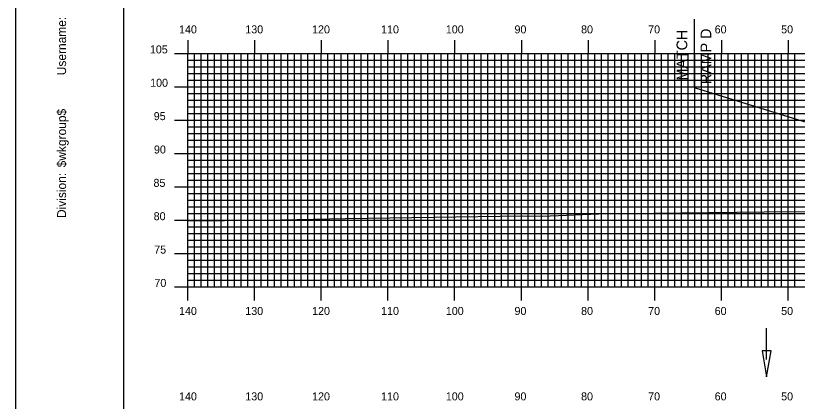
# Model space of a CAD drawing. Extents: x 1756282 to 1756625, y 442591 to 442811.
# Drawn here: x 1756281.8 to 1756398.9, y 442651.5 to 442709.3 of the extents above; entities that cross this region are included whole.
import ezdxf

# ---------------------------------------------------------------- set-up
doc = ezdxf.new("R2010")
doc.units = 0
for name, color, linetype in [('ANNOTATION', 7, 'Continuous'), ('BORDER', 7, 'Continuous'), ('D_Drainage_Ditch_Line', 7, 'Continuous'), ('D_Roadway_Centerline', 7, 'Continuous'), ('D_Roadway_SubGrade', 7, 'Continuous'), ('H_V ANNOTATION', 7, 'Continuous'), ('MAJOR', 7, 'Continuous'), ('MINOR', 7, 'Continuous'), ('PLOT BOUNDARY', 7, 'Continuous'), ('S_Roadway_Centerline', 7, 'Continuous')]:
    doc.layers.add(name, color=color, linetype=linetype)

msp = doc.modelspace()

# ---------------------------------------------------------------- linework, layer by layer
at = {"layer": 'BORDER'}
msp.add_lwpolyline([(1756297.97, 442596.67), (1756617.97, 442596.67), (1756617.97, 442806.67), (1756297.97, 442806.67)], close=True, dxfattribs=at)
at = {"layer": 'D_Drainage_Ditch_Line'}
msp.add_line((1756394.32, 442657.8), (1756394.32, 442662.5), dxfattribs=at)
msp.add_lwpolyline([(1756394.98, 442659.11), (1756393.67, 442659.11), (1756394.32, 442655.18)], close=True, dxfattribs=at)
at = {"layer": 'D_Roadway_Centerline'}
msp.add_lwpolyline([(1756383.48, 442698.56), (1756400.39, 442693.34), (1756401.23, 442693.06), (1756401.36, 442693.02), (1756402.56, 442692.63), (1756402.58, 442692.63), (1756402.66, 442692.6), (1756402.71, 442692.59), (1756403.03, 442692.48), (1756403.18, 442692.44), (1756404.11, 442692.13), (1756404.35, 442692.06), (1756405.57, 442691.66), (1756405.6, 442691.65), (1756405.76, 442691.6), (1756406.02, 442691.52), (1756407.03, 442691.19), (1756407.38, 442691.08), (1756409.6, 442690.36)], dxfattribs=at)
at = {"layer": 'D_Roadway_SubGrade'}
msp.add_line((1756383.48, 442708.78), (1756383.48, 442698.56), dxfattribs=at)
at = {"layer": 'MAJOR'}
for p, q in [((1756307.57, 442705.67), (1756307.57, 442703.67)), ((1756317.57, 442705.67), (1756317.57, 442703.67)), ((1756327.57, 442705.67), (1756327.57, 442703.67)), ((1756337.57, 442705.67), (1756337.57, 442703.67)), ((1756347.57, 442705.67), (1756347.57, 442703.67)), ((1756357.57, 442705.67), (1756357.57, 442703.67)), ((1756367.57, 442705.67), (1756367.57, 442703.67)), ((1756377.57, 442705.67), (1756377.57, 442703.67)), ((1756387.57, 442705.67), (1756387.57, 442703.67)), ((1756397.57, 442705.67), (1756397.57, 442703.67)), ((1756305.57, 442703.67), (1756307.57, 442703.67)), ((1756307.57, 442703.67), (1756587.57, 442703.67)), ((1756307.57, 442668.67), (1756307.57, 442703.67)), ((1756307.57, 442668.67), (1756307.57, 442703.67)), ((1756307.57, 442703.67), (1756587.57, 442703.67)), ((1756317.57, 442668.67), (1756317.57, 442703.67)), ((1756327.57, 442668.67), (1756327.57, 442703.67)), ((1756337.57, 442668.67), (1756337.57, 442703.67)), ((1756347.57, 442668.67), (1756347.57, 442703.67)), ((1756357.57, 442668.67), (1756357.57, 442703.67)), ((1756367.57, 442668.67), (1756367.57, 442703.67)), ((1756377.57, 442668.67), (1756377.57, 442703.67)), ((1756387.57, 442668.67), (1756387.57, 442703.67)), ((1756397.57, 442668.67), (1756397.57, 442703.67)), ((1756305.57, 442698.67), (1756307.57, 442698.67)), ((1756307.57, 442698.67), (1756587.57, 442698.67)), ((1756305.57, 442693.67), (1756307.57, 442693.67)), ((1756307.57, 442693.67), (1756587.57, 442693.67)), ((1756305.57, 442688.67), (1756307.57, 442688.67)), ((1756307.57, 442688.67), (1756587.57, 442688.67)), ((1756305.57, 442683.67), (1756307.57, 442683.67)), ((1756307.57, 442683.67), (1756587.57, 442683.67)), ((1756305.57, 442678.67), (1756307.57, 442678.67)), ((1756307.57, 442678.67), (1756587.57, 442678.67)), ((1756305.57, 442673.67), (1756307.57, 442673.67)), ((1756307.57, 442673.67), (1756587.57, 442673.67)), ((1756305.57, 442668.67), (1756307.57, 442668.67)), ((1756307.57, 442668.67), (1756587.57, 442668.67)), ((1756307.57, 442668.67), (1756587.57, 442668.67)), ((1756307.57, 442666.66), (1756307.57, 442668.67)), ((1756317.57, 442666.66), (1756317.57, 442668.67)), ((1756327.57, 442666.66), (1756327.57, 442668.67)), ((1756337.57, 442666.66), (1756337.57, 442668.67)), ((1756347.57, 442666.66), (1756347.57, 442668.67)), ((1756357.57, 442666.66), (1756357.57, 442668.67)), ((1756367.57, 442666.66), (1756367.57, 442668.67)), ((1756377.57, 442666.66), (1756377.57, 442668.67)), ((1756387.57, 442666.66), (1756387.57, 442668.67)), ((1756397.57, 442666.66), (1756397.57, 442668.67))]:
    msp.add_line(p, q, dxfattribs=at)
at = {"layer": 'MINOR'}
for p, q in [((1756307.57, 442702.67), (1756587.57, 442702.67)), ((1756307.57, 442702.67), (1756309.57, 442702.67)), ((1756308.57, 442668.67), (1756308.57, 442703.67)), ((1756309.57, 442668.67), (1756309.57, 442703.67)), ((1756310.57, 442668.67), (1756310.57, 442703.67)), ((1756311.57, 442668.67), (1756311.57, 442703.67)), ((1756312.57, 442668.67), (1756312.57, 442703.67)), ((1756313.57, 442668.67), (1756313.57, 442703.67)), ((1756314.57, 442668.67), (1756314.57, 442703.67)), ((1756315.57, 442668.67), (1756315.57, 442703.67)), ((1756316.57, 442668.67), (1756316.57, 442703.67)), ((1756318.57, 442668.67), (1756318.57, 442703.67)), ((1756319.57, 442668.67), (1756319.57, 442703.67)), ((1756320.57, 442668.67), (1756320.57, 442703.67)), ((1756321.57, 442668.67), (1756321.57, 442703.67)), ((1756322.57, 442668.67), (1756322.57, 442703.67)), ((1756323.57, 442668.67), (1756323.57, 442703.67)), ((1756324.57, 442668.67), (1756324.57, 442703.67)), ((1756325.57, 442668.67), (1756325.57, 442703.67)), ((1756326.57, 442668.67), (1756326.57, 442703.67)), ((1756328.57, 442668.67), (1756328.57, 442703.67)), ((1756329.57, 442668.67), (1756329.57, 442703.67)), ((1756330.57, 442668.67), (1756330.57, 442703.67)), ((1756331.57, 442668.67), (1756331.57, 442703.67)), ((1756332.57, 442668.67), (1756332.57, 442703.67)), ((1756333.57, 442668.67), (1756333.57, 442703.67)), ((1756334.57, 442668.67), (1756334.57, 442703.67)), ((1756335.57, 442668.67), (1756335.57, 442703.67)), ((1756336.57, 442668.67), (1756336.57, 442703.67)), ((1756338.57, 442668.67), (1756338.57, 442703.67)), ((1756339.57, 442668.67), (1756339.57, 442703.67)), ((1756340.57, 442668.67), (1756340.57, 442703.67)), ((1756341.57, 442668.67), (1756341.57, 442703.67)), ((1756342.57, 442668.67), (1756342.57, 442703.67)), ((1756343.57, 442668.67), (1756343.57, 442703.67)), ((1756344.57, 442668.67), (1756344.57, 442703.67)), ((1756345.57, 442668.67), (1756345.57, 442703.67)), ((1756346.57, 442668.67), (1756346.57, 442703.67)), ((1756348.57, 442668.67), (1756348.57, 442703.67)), ((1756349.57, 442668.67), (1756349.57, 442703.67)), ((1756350.57, 442668.67), (1756350.57, 442703.67)), ((1756351.57, 442668.67), (1756351.57, 442703.67)), ((1756352.57, 442668.67), (1756352.57, 442703.67)), ((1756353.57, 442668.67), (1756353.57, 442703.67)), ((1756354.57, 442668.67), (1756354.57, 442703.67)), ((1756355.57, 442668.67), (1756355.57, 442703.67)), ((1756356.57, 442668.67), (1756356.57, 442703.67)), ((1756358.57, 442668.67), (1756358.57, 442703.67)), ((1756359.57, 442668.67), (1756359.57, 442703.67)), ((1756360.57, 442668.67), (1756360.57, 442703.67)), ((1756361.57, 442668.67), (1756361.57, 442703.67)), ((1756362.57, 442668.67), (1756362.57, 442703.67)), ((1756363.57, 442668.67), (1756363.57, 442703.67)), ((1756364.57, 442668.67), (1756364.57, 442703.67)), ((1756365.57, 442668.67), (1756365.57, 442703.67)), ((1756366.57, 442668.67), (1756366.57, 442703.67)), ((1756368.57, 442668.67), (1756368.57, 442703.67)), ((1756369.57, 442668.67), (1756369.57, 442703.67)), ((1756370.57, 442668.67), (1756370.57, 442703.67)), ((1756371.57, 442668.67), (1756371.57, 442703.67)), ((1756372.57, 442668.67), (1756372.57, 442703.67)), ((1756373.57, 442668.67), (1756373.57, 442703.67)), ((1756374.57, 442668.67), (1756374.57, 442703.67)), ((1756375.57, 442668.67), (1756375.57, 442703.67)), ((1756376.57, 442668.67), (1756376.57, 442703.67)), ((1756378.57, 442668.67), (1756378.57, 442703.67)), ((1756379.57, 442668.67), (1756379.57, 442703.67)), ((1756380.57, 442668.67), (1756380.57, 442703.67)), ((1756381.57, 442668.67), (1756381.57, 442703.67)), ((1756382.57, 442668.67), (1756382.57, 442703.67)), ((1756383.57, 442668.67), (1756383.57, 442703.67)), ((1756384.57, 442668.67), (1756384.57, 442703.67)), ((1756385.57, 442668.67), (1756385.57, 442703.67)), ((1756386.57, 442668.67), (1756386.57, 442703.67)), ((1756388.57, 442668.67), (1756388.57, 442703.67)), ((1756389.57, 442668.67), (1756389.57, 442703.67)), ((1756390.57, 442668.67), (1756390.57, 442703.67)), ((1756391.57, 442668.67), (1756391.57, 442703.67)), ((1756392.57, 442668.67), (1756392.57, 442703.67)), ((1756393.57, 442668.67), (1756393.57, 442703.67)), ((1756394.57, 442668.67), (1756394.57, 442703.67)), ((1756395.57, 442668.67), (1756395.57, 442703.67)), ((1756396.57, 442668.67), (1756396.57, 442703.67)), ((1756398.57, 442668.67), (1756398.57, 442703.67)), ((1756307.57, 442701.67), (1756587.57, 442701.67)), ((1756307.57, 442701.67), (1756309.57, 442701.67)), ((1756307.57, 442700.67), (1756587.57, 442700.67)), ((1756307.57, 442700.67), (1756309.57, 442700.67)), ((1756307.57, 442699.67), (1756587.57, 442699.67)), ((1756307.57, 442699.67), (1756309.57, 442699.67)), ((1756307.57, 442697.67), (1756587.57, 442697.67)), ((1756307.57, 442697.67), (1756309.57, 442697.67)), ((1756307.57, 442696.67), (1756587.57, 442696.67)), ((1756307.57, 442696.67), (1756309.57, 442696.67)), ((1756307.57, 442695.67), (1756587.57, 442695.67)), ((1756307.57, 442695.67), (1756309.57, 442695.67)), ((1756307.57, 442694.67), (1756587.57, 442694.67)), ((1756307.57, 442694.67), (1756309.57, 442694.67)), ((1756307.57, 442692.67), (1756587.57, 442692.67)), ((1756307.57, 442692.67), (1756309.57, 442692.67)), ((1756307.57, 442691.67), (1756587.57, 442691.67)), ((1756307.57, 442691.67), (1756309.57, 442691.67)), ((1756307.57, 442690.67), (1756587.57, 442690.67)), ((1756307.57, 442690.67), (1756309.57, 442690.67)), ((1756307.57, 442689.67), (1756587.57, 442689.67)), ((1756307.57, 442689.67), (1756309.57, 442689.67)), ((1756307.57, 442687.67), (1756587.57, 442687.67)), ((1756307.57, 442687.67), (1756309.57, 442687.67)), ((1756307.57, 442686.67), (1756587.57, 442686.67)), ((1756307.57, 442686.67), (1756309.57, 442686.67)), ((1756307.57, 442685.67), (1756587.57, 442685.67)), ((1756307.57, 442685.67), (1756309.57, 442685.67)), ((1756307.57, 442684.67), (1756587.57, 442684.67)), ((1756307.57, 442684.67), (1756309.57, 442684.67)), ((1756307.57, 442682.67), (1756587.57, 442682.67)), ((1756307.57, 442682.67), (1756309.57, 442682.67)), ((1756307.57, 442681.67), (1756587.57, 442681.67)), ((1756307.57, 442681.67), (1756309.57, 442681.67)), ((1756307.57, 442680.67), (1756587.57, 442680.67)), ((1756307.57, 442680.67), (1756309.57, 442680.67)), ((1756307.57, 442679.67), (1756587.57, 442679.67)), ((1756307.57, 442679.67), (1756309.57, 442679.67)), ((1756307.57, 442677.67), (1756587.57, 442677.67)), ((1756307.57, 442677.67), (1756309.57, 442677.67)), ((1756307.57, 442676.67), (1756587.57, 442676.67)), ((1756307.57, 442676.67), (1756309.57, 442676.67)), ((1756307.57, 442675.67), (1756587.57, 442675.67)), ((1756307.57, 442675.67), (1756309.57, 442675.67)), ((1756307.57, 442674.67), (1756587.57, 442674.67)), ((1756307.57, 442674.67), (1756309.57, 442674.67)), ((1756307.57, 442672.67), (1756587.57, 442672.67)), ((1756307.57, 442672.67), (1756309.57, 442672.67)), ((1756307.57, 442671.67), (1756587.57, 442671.67)), ((1756307.57, 442671.67), (1756309.57, 442671.67)), ((1756307.57, 442670.67), (1756587.57, 442670.67)), ((1756307.57, 442670.67), (1756309.57, 442670.67)), ((1756307.57, 442669.67), (1756587.57, 442669.67)), ((1756307.57, 442669.67), (1756309.57, 442669.67))]:
    msp.add_line(p, q, dxfattribs=at)
at = {"layer": 'PLOT BOUNDARY'}
msp.add_lwpolyline([(1756281.78, 442590.55), (1756621.78, 442590.55), (1756621.78, 442810.55), (1756281.78, 442810.55)], close=True, dxfattribs=at)
at = {"layer": 'S_Roadway_Centerline'}
msp.add_lwpolyline([(1756307.57, 442678.65), (1756308.9, 442678.63), (1756313.08, 442678.64), (1756319.12, 442678.69), (1756331.23, 442678.95), (1756357.71, 442679.32), (1756360.7, 442679.28), (1756369.19, 442679.62), (1756398.08, 442679.98), (1756402.56, 442679.91)], dxfattribs=at)

# ---------------------------------------------------------------- texts
at = {"layer": 'ANNOTATION'}
for s, p in [('RAMP D', (1756386.03, 442699.07)), ('MATCH', (1756382.43, 442699.61))]:
    msp.add_text(s, height=1.6, rotation=90, dxfattribs=at).set_placement(p)
at = {"layer": 'BORDER'}
for s, p in [('Username:', (1756289.34, 442700.4)), ('Username:', (1756289.34, 442700.4)), ('$wkgroup$', (1756289.34, 442686.6)), ('$wkgroup$', (1756289.34, 442686.6)), ('Division:', (1756289.34, 442679)), ('Division:', (1756289.34, 442679))]:
    msp.add_text(s, height=1.339, rotation=90, dxfattribs=at).set_placement(p)
at = {"layer": 'H_V ANNOTATION'}
for s, p in [('140', (1756306.27, 442706.67)), ('130', (1756316.2, 442706.67)), ('120', (1756326.21, 442706.67)), ('110', (1756336.55, 442706.67)), ('100', (1756346.25, 442706.67)), ('90', (1756356.54, 442706.67)), ('80', (1756366.52, 442706.67)), ('70', (1756376.57, 442706.67)), ('60', (1756386.54, 442706.67)), ('50', (1756396.5, 442706.67)), ('105', (1756301.9, 442703.67)), ('100', (1756301.94, 442698.67)), ('95', (1756302.48, 442693.67)), ('90', (1756302.51, 442688.67)), ('85', (1756302.44, 442683.67)), ('80', (1756302.47, 442678.67)), ('75', (1756302.55, 442673.67)), ('70', (1756302.58, 442668.67)), ('140', (1756306.27, 442664.47)), ('130', (1756316.2, 442664.47)), ('120', (1756326.21, 442664.47)), ('110', (1756336.55, 442664.47)), ('100', (1756346.25, 442664.47)), ('90', (1756356.54, 442664.47)), ('80', (1756366.52, 442664.47)), ('70', (1756376.57, 442664.47)), ('60', (1756386.54, 442664.47)), ('50', (1756396.5, 442664.47)), ('140', (1756306.27, 442651.67)), ('130', (1756316.2, 442651.67)), ('120', (1756326.21, 442651.67)), ('110', (1756336.55, 442651.67)), ('100', (1756346.25, 442651.67)), ('90', (1756356.54, 442651.67)), ('80', (1756366.52, 442651.67)), ('70', (1756376.57, 442651.67)), ('60', (1756386.54, 442651.67)), ('50', (1756396.5, 442651.67))]:
    msp.add_text(s, height=1.2, dxfattribs=at).set_placement(p)
at = {"layer": 'MAJOR'}
msp.add_text('-', height=0.012, dxfattribs=at).set_placement((1756307.56, 442668.67))

doc.saveas('drawing.dxf')
